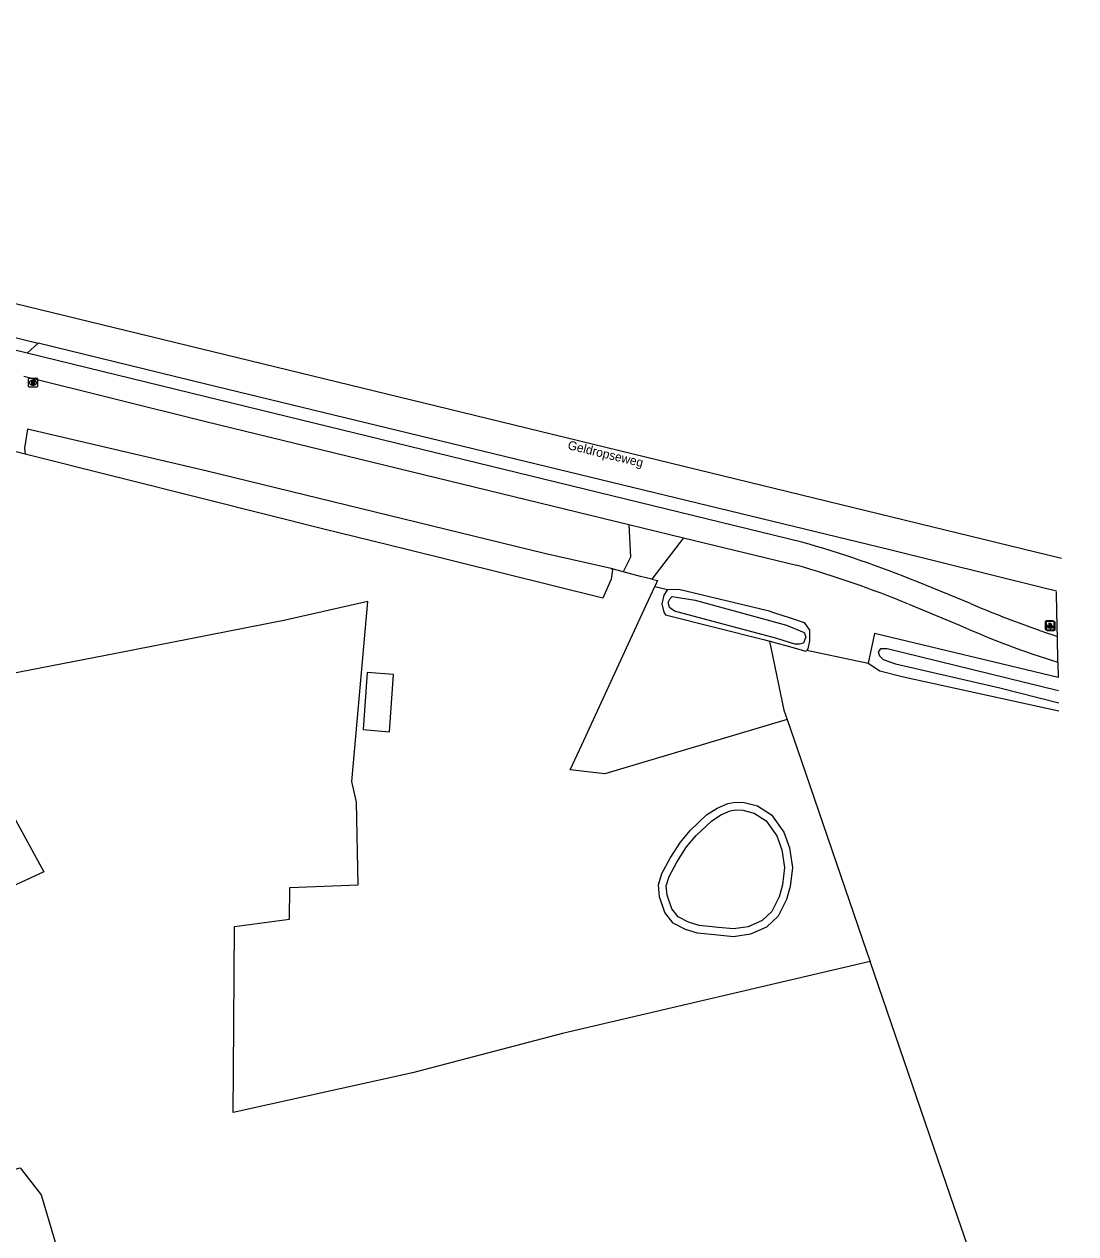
# Model space of a CAD drawing. Extents: x 163863 to 164644, y 379566 to 382155.
# Drawn here: x 164479.7 to 164597.2, y 382019.3 to 382154.5 of the extents above; entities that cross this region are included whole.
import ezdxf

# ---------------------------------------------------------------- set-up
doc = ezdxf.new("R2010")
doc.units = 0
for name, color, linetype in [('IMGEO_Berm_groen', 7, 'Continuous'), ('IMGEO_Erf', 7, 'Continuous'), ('IMGEO_Fietspad_gesloten', 7, 'Continuous'), ('IMGEO_Grasland_agrarisch', 7, 'Continuous'), ('IMGEO_Grasland_overig', 7, 'Continuous'), ('IMGEO_Groenvoorziening', 7, 'Continuous'), ('IMGEO_Lichtpunt', 7, 'Continuous'), ('IMGEO_Loofbos', 7, 'Continuous'), ('IMGEO_Meer_plas_ven_vijver', 7, 'Continuous'), ('IMGEO_Openbare_ruimte_label', 7, 'Continuous'), ('IMGEO_Pand', 7, 'Continuous'), ('IMGEO_Rijbaan_lokaal_onverhard', 7, 'Continuous'), ('IMGEO_Rijbaan_regionaal_gesloten', 7, 'Continuous'), ('IMGEO_Rioolput', 7, 'Continuous'), ('IMGEO_Sloot', 7, 'Continuous'), ('IMGEO_Voetpad_open', 7, 'Continuous'), ('IMGEO_Waterloop', 7, 'Continuous')]:
    doc.layers.add(name, color=color, linetype=linetype)

msp = doc.modelspace()

# ---------------------------------------------------------------- linework, layer by layer
at = {"layer": 'IMGEO_Berm_groen'}
for points in [[(164595.15, 382087.13), (164595.08, 382090.8), (164595.08, 382091.04)], [(164595.15, 382087.13), (164595.15, 382087.13)], [(164595.17, 382086.08), (164595.15, 382087.13)], [(164595.23, 382083.2), (164595.26, 382081.49)]]:
    msp.add_lwpolyline(points, dxfattribs=at)
at = {"layer": 'IMGEO_Erf'}
msp.add_lwpolyline([(164560.15, 382067.52), (164561.64, 382067.12), (164563.24, 382066.11), (164564.61, 382064.19), (164565.24, 382062.43), (164565.55, 382060.24), (164565.31, 382058.13), (164564.88, 382056.65), (164563.98, 382054.81), (164562.65, 382053.56), (164560.86, 382052.78), (164558.98, 382052.5), (164557.22, 382052.66), (164554.95, 382052.89), (164553.62, 382053.32), (164552.22, 382054.03), (164551.32, 382055.2), (164550.69, 382056.96), (164550.58, 382058.29), (164550.97, 382059.58), (164551.9, 382061.3), (164553.04, 382063.06), (164554.17, 382064.43), (164555.97, 382066.11), (164557.14, 382066.89), (164558.36, 382067.4), (164559.18, 382067.55), (164560.15, 382067.52)], dxfattribs=at)
at = {"layer": 'IMGEO_Fietspad_gesloten'}
for points in [[(164480.06, 382117.73), (164432.23, 382129.4)], [(164566.61, 382096.62), (164500, 382112.87), (164480.06, 382117.73)], [(164479.66, 382115.15), (164500, 382110.11), (164547.27, 382098.59)], [(164553.37, 382097.11), (164566.02, 382094.03)], [(164585.46, 382089.75), (164579.54, 382092.17)], [(164578.55, 382089.67), (164584.23, 382087.34)], [(164595.23, 382083.2), (164595.17, 382086.08)]]:
    msp.add_lwpolyline(points, dxfattribs=at)
for centre, radius, start, end in [((164532.11, 381975.37), 126.06, 67.8989, 74.1185), ((164534.05, 381981.81), 116.68, 67.5816, 74.1012), ((164631.62, 382197.16), 116.91, 246.7456, 251.8362), ((164621.56, 382169.88), 90.59, 245.6621, 253.1015)]:
    msp.add_arc(centre, radius, start, end, dxfattribs=at)
at = {"layer": 'IMGEO_Grasland_agrarisch'}
for points in [[(164574.25, 382049.73), (164539.85, 382041.68), (164523.11, 382037.28), (164503.08, 382032.86), (164503.12, 382037.46), (164503.23, 382053.66), (164509.38, 382054.47), (164509.39, 382058.02), (164517.02, 382058.31), (164516.85, 382067.53), (164516.34, 382069.87), (164518.12, 382089.97), (164508.72, 382087.84), (164489.95, 382084.16), (164470.87, 382080.47)], [(164474.51, 382073.3), (164481.92, 382059.76), (164475.75, 382056.93)]]:
    msp.add_lwpolyline(points, dxfattribs=at)
at = {"layer": 'IMGEO_Grasland_overig'}
msp.add_lwpolyline([(164498.03, 382004.23), (164485.7, 382001.51), (164473.39, 381998.73), (164467.22, 382022.66), (164467.02, 382023.39), (164479.26, 382026.66), (164481.61, 382023.65), (164483.42, 382017.63), (164484.77, 382010.15), (164484.92, 382009.26), (164491.77, 382011.05), (164494.28, 382009.65), (164498.03, 382004.23)], dxfattribs=at)
at = {"layer": 'IMGEO_Groenvoorziening'}
for points in [[(164479.82, 382106.45), (164477.07, 382107.14)], [(164546.64, 382093.3), (164545.32, 382093.66)], [(164564.98, 382076.78), (164544.61, 382070.72), (164540.74, 382071.15), (164542.03, 382073.97), (164548.98, 382089.07), (164550.17, 382091.64)], [(164549.84, 382092.47), (164550.48, 382092.32), (164550.17, 382091.64)], [(164550.17, 382091.64), (164551.6, 382091.31)], [(164551.6, 382091.31), (164551.18, 382090.67), (164550.97, 382089.72), (164551.18, 382088.77), (164551.38, 382088.47), (164562.34, 382085.73), (164562.99, 382085.54)], [(164551.6, 382091.31), (164552.87, 382091.36), (164562.82, 382088.96), (164563.57, 382088.71), (164565.2, 382088.19), (164566.87, 382087.63), (164567.45, 382086.76), (164567.48, 382085.57), (164567.29, 382084.7), (164567.18, 382084.52)], [(164595.26, 382081.49), (164574.74, 382086.41), (164574.03, 382083.08)]]:
    msp.add_lwpolyline(points, dxfattribs=at)
at = {"layer": 'IMGEO_Lichtpunt'}
for p, q in [((164593.81, 382087.7), (164593.81, 382086.9)), ((164593.81, 382087.7), (164593.81, 382086.9)), ((164594.71, 382087.8), (164593.9, 382087.8)), ((164594.71, 382087.8), (164593.9, 382087.8)), ((164593.92, 382087.63), (164593.92, 382086.82)), ((164593.92, 382087.63), (164593.92, 382086.82)), ((164594.82, 382087.73), (164594.01, 382087.73)), ((164594.82, 382087.73), (164594.01, 382087.73)), ((164594.8, 382086.9), (164594.8, 382087.7)), ((164594.8, 382086.9), (164594.8, 382087.7)), ((164594.91, 382086.82), (164594.91, 382087.63)), ((164594.91, 382086.82), (164594.91, 382087.63)), ((164593.9, 382086.8), (164594.71, 382086.8)), ((164593.9, 382086.8), (164594.71, 382086.8)), ((164594.01, 382086.73), (164594.82, 382086.73)), ((164594.01, 382086.73), (164594.82, 382086.73))]:
    msp.add_line(p, q, dxfattribs=at)
for points in [[(164594.18, 382087.37), (164594.22, 382087.34), (164594.03, 382087.08), (164593.99, 382087.1), (164594.18, 382087.37)], [(164594.29, 382087.29), (164594.33, 382087.27), (164594.14, 382087), (164594.1, 382087.03), (164594.29, 382087.29)], [(164594.28, 382087.32), (164594.33, 382087.32), (164594.33, 382087), (164594.28, 382087), (164594.28, 382087.32)], [(164594.39, 382087.34), (164594.43, 382087.37), (164594.62, 382087.1), (164594.58, 382087.08), (164594.39, 382087.34)], [(164594.39, 382087.25), (164594.44, 382087.25), (164594.44, 382086.92), (164594.39, 382086.92), (164594.39, 382087.25)], [(164594.5, 382087.27), (164594.54, 382087.29), (164594.73, 382087.03), (164594.69, 382087), (164594.5, 382087.27)]]:
    msp.add_lwpolyline(points, dxfattribs=at)
for centre in [(164594.31, 382087.5), (164594.42, 382087.43)]:
    msp.add_circle(centre, 0.0994, dxfattribs=at)
for centre, start, end in [((164593.9, 382087.7), 90, 180), ((164593.9, 382087.7), 90, 180), ((164594.01, 382087.63), 90, 180), ((164594.01, 382087.63), 90, 180), ((164594.71, 382087.7), 0, 90), ((164594.71, 382087.7), 0, 90), ((164594.82, 382087.63), 0, 90), ((164594.82, 382087.63), 0, 90), ((164593.9, 382086.9), 180, 270), ((164593.9, 382086.9), 180, 270), ((164594.01, 382086.82), 180, 270), ((164594.01, 382086.82), 180, 270), ((164594.71, 382086.9), 270, 0), ((164594.71, 382086.9), 270, 360), ((164594.82, 382086.82), 270, 0), ((164594.82, 382086.82), 270, 360)]:
    msp.add_arc(centre, 0.0946, start, end, dxfattribs=at)
at = {"layer": 'IMGEO_Loofbos'}
for points in [[(164562.99, 382085.54), (164564.61, 382077.84), (164564.98, 382076.78)], [(164567.18, 382084.52), (164567.08, 382084.38), (164564.87, 382085.01), (164564.01, 382085.25), (164562.99, 382085.54)], [(164567.18, 382084.52), (164574.03, 382083.08)], [(164574.03, 382083.08), (164575.32, 382082.24), (164577.96, 382081.55), (164595.34, 382077.74), (164595.34, 382077.74)], [(164564.98, 382076.78), (164566.54, 382072.23), (164573.89, 382050.78), (164574.25, 382049.73)], [(164597.22, 381982.52), (164591.3, 382000), (164588.99, 382006.72), (164583.24, 382023.49), (164574.25, 382049.73)]]:
    msp.add_lwpolyline(points, dxfattribs=at)
at = {"layer": 'IMGEO_Meer_plas_ven_vijver'}
msp.add_lwpolyline([(164564.45, 382058.3), (164564.07, 382056.96), (164563.27, 382055.34), (164562.17, 382054.3), (164560.61, 382053.62), (164558.96, 382053.38), (164557.3, 382053.53), (164555.13, 382053.75), (164553.96, 382054.14), (164552.79, 382054.72), (164552.1, 382055.62), (164551.55, 382057.15), (164551.46, 382058.2), (164551.78, 382059.24), (164552.66, 382060.85), (164553.74, 382062.54), (164554.81, 382063.83), (164556.51, 382065.42), (164557.56, 382066.12), (164558.61, 382066.56), (164559.24, 382066.68), (164560.02, 382066.65), (164561.28, 382066.31), (164562.63, 382065.46), (164563.83, 382063.78), (164564.38, 382062.22), (164564.67, 382060.23), (164564.45, 382058.3)], dxfattribs=at)
at = {"layer": 'IMGEO_Pand'}
msp.add_lwpolyline([(164518.05, 382082.03), (164517.58, 382075.67), (164520.54, 382075.41), (164520.97, 382081.81), (164518.05, 382082.03)], dxfattribs=at)
at = {"layer": 'IMGEO_Rijbaan_lokaal_onverhard'}
for points in [[(164547.27, 382098.59), (164547.48, 382094.92), (164546.64, 382093.3)], [(164547.27, 382098.59), (164553.37, 382097.11)], [(164553.37, 382097.11), (164549.84, 382092.47)], [(164549.84, 382092.47), (164548.6, 382092.76), (164546.64, 382093.3)]]:
    msp.add_lwpolyline(points, dxfattribs=at)
at = {"layer": 'IMGEO_Rijbaan_regionaal_gesloten'}
for points in [[(164350.86, 382154.51), (164352.35, 382154.14), (164422.81, 382136.88), (164448.24, 382130.7), (164525.74, 382111.86), (164595.63, 382094.81)], [(164431.4, 382131.09), (164481.27, 382118.87)], [(164595.08, 382091.12), (164593.39, 382091.53), (164576.43, 382095.76), (164500, 382114.28), (164481.27, 382118.87)]]:
    msp.add_lwpolyline(points, dxfattribs=at)
at = {"layer": 'IMGEO_Rioolput'}
for p, q in [((164480.2, 382114.01), (164480.2, 382114.87)), ((164480.28, 382114.94), (164481.13, 382114.94)), ((164480.69, 382114.72), (164480.71, 382114.72)), ((164481.2, 382114.87), (164481.2, 382114.01)), ((164481.13, 382113.94), (164480.28, 382113.94)), ((164480.71, 382114.16), (164480.69, 382114.16))]:
    msp.add_line(p, q, dxfattribs=at)
for points in [[(164480.2, 382114.01), (164480.2, 382114.87)], [(164480.28, 382114.94), (164481.13, 382114.94)], [(164480.79, 382114.64), (164480.54, 382114.64), (164480.54, 382114.24)], [(164481.2, 382114.87), (164481.2, 382114.01)], [(164481.13, 382113.94), (164480.28, 382113.94)], [(164480.54, 382114.24), (164480.66, 382114.24), (164480.66, 382114.4), (164480.67, 382114.4)], [(164480.72, 382114.56), (164480.66, 382114.56), (164480.66, 382114.48)], [(164480.66, 382114.48), (164480.71, 382114.48)], [(164480.72, 382114.37), (164480.79, 382114.24), (164480.93, 382114.24), (164480.87, 382114.37)]]:
    msp.add_lwpolyline(points, dxfattribs=at)
for centre, radius, start, end in [((164480.28, 382114.87), 0.0765, 91.552, 178.448), ((164480.28, 382114.87), 0.0765, 91.552, 178.448), ((164480.79, 382114.53), 0.109, 350.3612, 89.416), ((164481.13, 382114.87), 0.0765, 1.552, 88.448), ((164481.13, 382114.87), 0.0765, 1.552, 88.448), ((164480.28, 382114.02), 0.0765, 181.552, 268.448), ((164480.28, 382114.02), 0.0765, 181.552, 268.448), ((164480.67, 382114.35), 0.0533, 26.0293, 88.6989), ((164480.7, 382114.67), 0.19, 274.7715, 282.9687), ((164480.72, 382114.46), 0.0964, 77.0061, 93.1865), ((164480.74, 382114.52), 0.0378, 276.6634, 79.6772), ((164480.79, 382114.53), 0.112, 277.5842, 350.9817), ((164480.77, 382114.31), 0.108, 29.5134, 73.7905), ((164481.13, 382114.02), 0.0765, 271.552, 358.448), ((164481.13, 382114.02), 0.0765, 271.552, 358.448)]:
    msp.add_arc(centre, radius, start, end, dxfattribs=at)
for centre, major_axis, ratio, start_param, end_param in [((164480.69, 382114.44), (-0.387, 0.002), 0.722429, 4.712389, 7.853982), ((164480.71, 382114.44), (-0.39, 0.002), 0.717154, 1.570796, 4.712389)]:
    msp.add_ellipse(centre, major_axis=major_axis, ratio=ratio, start_param=start_param, end_param=end_param, dxfattribs=at)
at = {"layer": 'IMGEO_Sloot'}
msp.add_lwpolyline([(164595.29, 382080), (164576.14, 382084.69), (164575.41, 382084.7), (164575.14, 382084.34), (164575.28, 382083.91), (164575.69, 382083.49), (164577.08, 382083), (164588.75, 382080.34), (164595.32, 382078.64)], dxfattribs=at)
at = {"layer": 'IMGEO_Voetpad_open'}
msp.add_lwpolyline([(164481.27, 382118.87), (164480.06, 382117.73)], dxfattribs=at)
at = {"layer": 'IMGEO_Waterloop'}
for points in [[(164545.32, 382093.66), (164537.87, 382095.33), (164500, 382104.57), (164480.07, 382109.25), (164479.77, 382107.13), (164479.82, 382106.45)], [(164545.32, 382093.66), (164545.44, 382093.5), (164545.3, 382092.48), (164544.39, 382090.34), (164522.31, 382095.81), (164513.2, 382098.08), (164500, 382101.39), (164479.82, 382106.45)], [(164566.79, 382085.33), (164566.34, 382085.2), (164565.84, 382085.22), (164563.83, 382085.83), (164552.37, 382088.88), (164551.82, 382089.3), (164551.66, 382089.88), (164551.89, 382090.3), (164552.11, 382090.54), (164554.7, 382090.12), (164564.91, 382087.32), (164566.87, 382086.52), (164567.05, 382086.04), (164566.79, 382085.33)]]:
    msp.add_lwpolyline(points, dxfattribs=at)

# ---------------------------------------------------------------- texts
at = {"layer": 'IMGEO_Openbare_ruimte_label'}
msp.add_text('Geldropseweg', height=1, rotation=346.3528, dxfattribs=at).set_placement((164540.38, 382107.02))

doc.saveas('drawing.dxf')
